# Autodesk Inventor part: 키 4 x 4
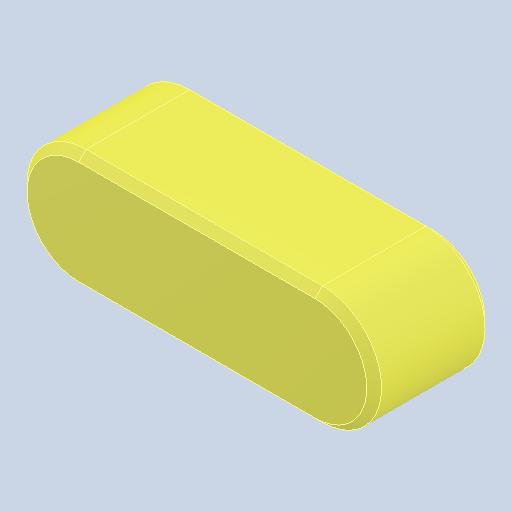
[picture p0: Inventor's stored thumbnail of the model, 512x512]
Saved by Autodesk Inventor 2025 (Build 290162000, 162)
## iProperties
Created: 2024-08
Part Number: 키 4 x 4
Material: 강철, 연강
Description: 키 및 해당 키홈
Document SubType Name: Modeling
Designer: Administrator
Density: 7.86 g/cm^3
Appearance: 기본값
Author: jhkim
Sending System: Autodesk Inventor 2025
Preprocessor: ST-DEVELOPER v20
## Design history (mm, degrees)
feature "Solid1"
node "솔리드1"
